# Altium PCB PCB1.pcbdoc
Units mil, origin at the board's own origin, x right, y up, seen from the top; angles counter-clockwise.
Board outline 5155 x 5410 mil, 2 copper layers (Top Layer, Bottom Layer); 94 components, 49 nets, 290 pads, 505 vias.
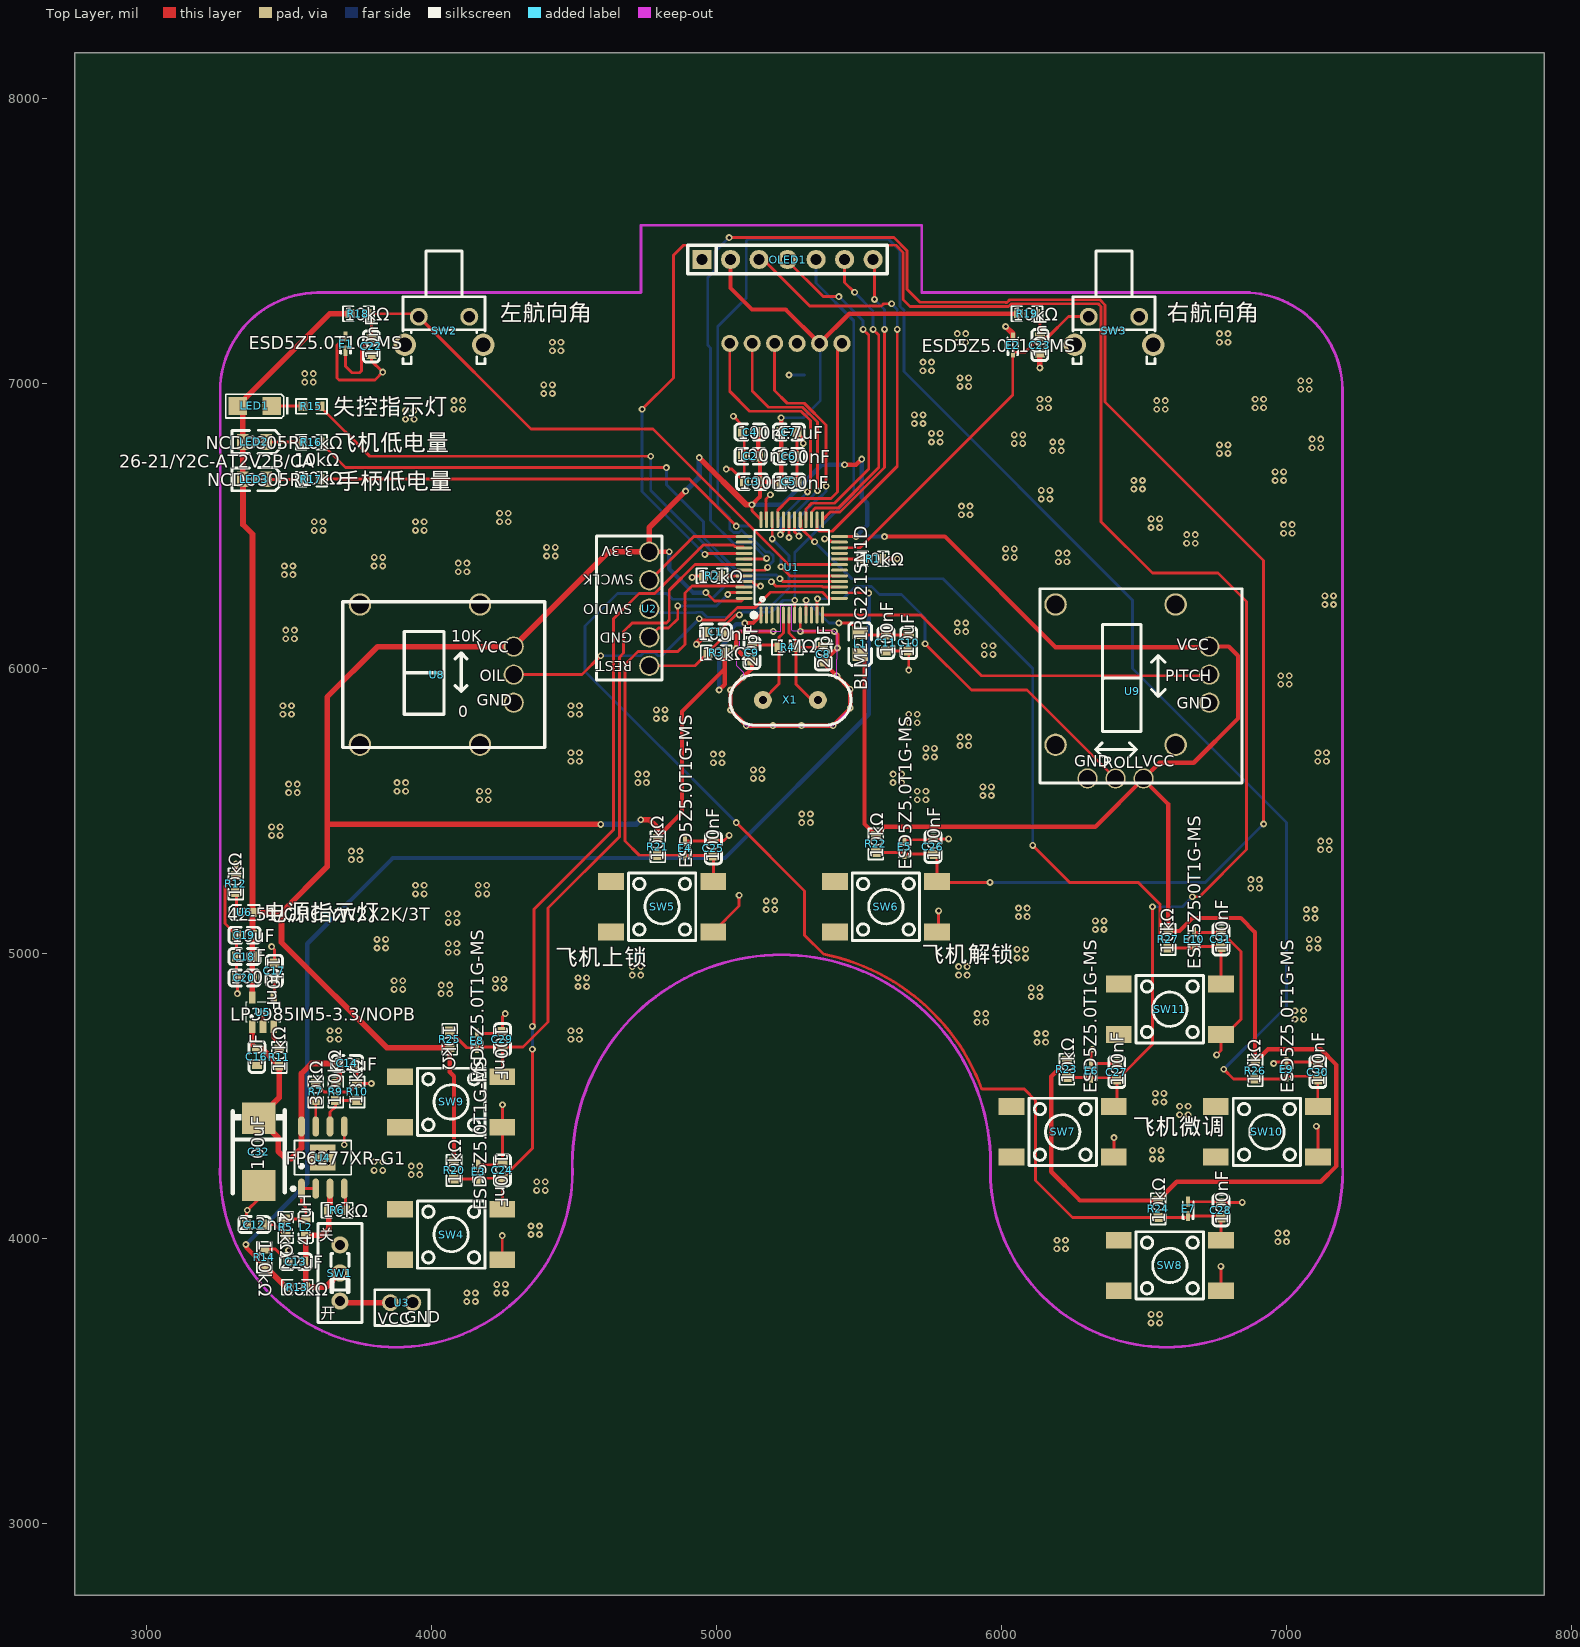
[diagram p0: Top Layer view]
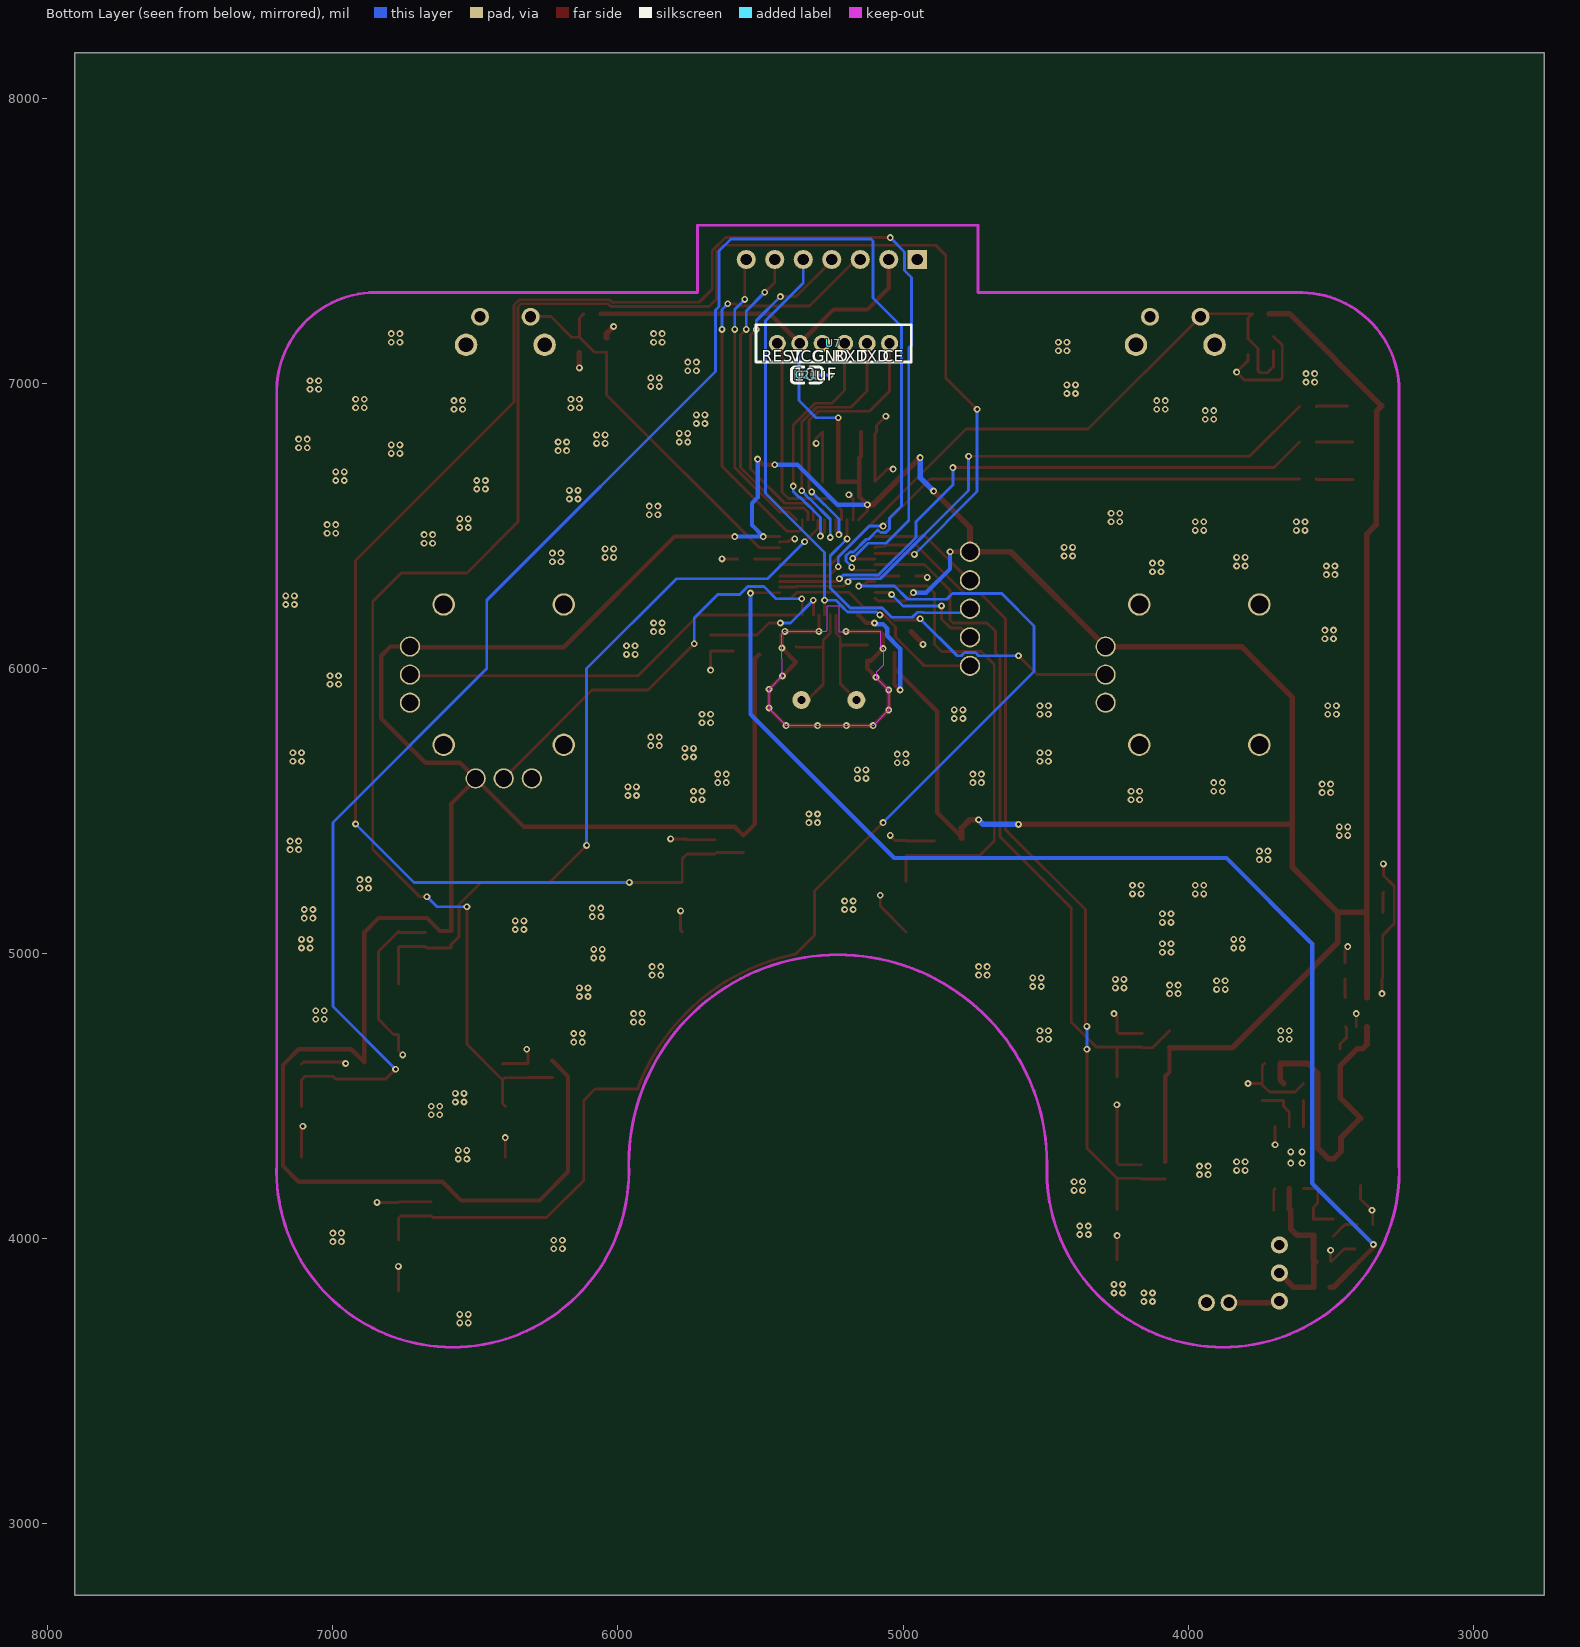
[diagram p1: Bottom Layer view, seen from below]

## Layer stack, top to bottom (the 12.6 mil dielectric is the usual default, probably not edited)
Top Layer: signal copper (thickness not stored)
Dielectric: dielectric 12.6, FR-4, Dk 4.8
Bottom Layer: signal copper (thickness not stored)

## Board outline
7905,2750 2750,2750 2750,8160 7905,8160

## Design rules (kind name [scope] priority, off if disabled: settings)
BoardOutlineClearance copperThickness1oz [All] p0: genericclearance=10 ignorepadtopadclearanceinfootprint=FALSE except(0: Arc-SplitContinuation Track-SplitContinuation SMDPad-SplitContinuation THPad-SplitContinuation Via-SplitContinuation Fill-SplitContinuation Poly-SplitContinuation Region-SplitContinuation Text-SplitContinuation; 6: Track-CutoutEdge SMDPad-CutoutEdge THPad-CutoutEdge Via-CutoutEdge Region-CutoutEdge; 11.8: Track-OutlineEdge SMDPad-OutlineEdge THPad-OutlineEdge Via-OutlineEdge Fill-OutlineEdge Region-OutlineEdge Poly-OutlineEdge Text-OutlineEdge Fill-CutoutEdge)
BoardOutlineClearance copperThickness2oz [All] p0: genericclearance=10 ignorepadtopadclearanceinfootprint=FALSE except(0: Arc-SplitContinuation Track-SplitContinuation SMDPad-SplitContinuation THPad-SplitContinuation Via-SplitContinuation Fill-SplitContinuation Poly-SplitContinuation Region-SplitContinuation Text-SplitContinuation; 6: Track-CutoutEdge SMDPad-CutoutEdge THPad-CutoutEdge Via-CutoutEdge Region-CutoutEdge; 11.8: Track-OutlineEdge SMDPad-OutlineEdge THPad-OutlineEdge Via-OutlineEdge Fill-OutlineEdge Region-OutlineEdge Poly-OutlineEdge Text-OutlineEdge Fill-CutoutEdge)
Clearance copperThickness1oz [(InNet('REST') OR InNet('OSC_OUT') OR InNet('OSC_IN') OR InNet('$1N3011') OR InNet('$1N4996') OR InNet('$1N6765') OR InNet('S1') OR InNet('S2') OR InNet('S3') OR InNet('S4') OR InNet('S5') OR InNet('S6') OR InNet('S7') OR InNet('S8') OR InNet('S9') OR InNet('S10') OR InNet('$1N4402') OR InNet('$1N8601') OR InNet('$1N8762') OR InNet('$1N8882') OR InNet('CS') OR InNet('MISO') OR InNet('MOSI') OR InNet('SCK') OR InNet('BOOT1') OR InNet('BOOT0') OR InNet('$1N5122') OR InNet('$1N5241') OR InNet('$1N5390') OR InNet('$1N6665') OR InNet('$1N8365') OR InNet('LED1') OR InNet('LED2') OR InNet('LED3') OR InNet('ROLL-ADC') OR InNet('PITCH-ADC') OR InNet('OIL-ADC') OR InNet('UART_TX') OR InNet('UART_RX') OR InNet('CE') OR InNet('RST') OR InNet('SWDIO') OR InNet('SWCLK'))] p1: gap=7 ignorepadtopadclearanceinfootprint=FALSE except(4: Track-Track; 6: Track-SMDPad SMDPad-SMDPad Track-THPad SMDPad-THPad THPad-THPad Track-Via SMDPad-Via THPad-Via Via-Via SMDPad-Fill THPad-Fill Via-Fill Fill-Fill Track-Region SMDPad-Region THPad-Region Via-Region Region-Region Track-Poly SMDPad-Poly THPad-Poly Via-Poly Fill-Poly Region-Poly Poly-Poly Track-Text SMDPad-Text THPad-Text Via-Text Fill-Text Region-Text Poly-Text Text-Text; 6.9: Track-Hole SMDPad-Hole THPad-Hole Via-Hole Fill-Hole Region-Hole Poly-Hole Text-Hole Sheet-Hole; 11.8: Track-Fill Fill-Region Track-Sheet SMDPad-Sheet THPad-Sheet Via-Sheet Fill-Sheet Region-Sheet Poly-Sheet Text-Sheet)
Clearance copperThickness2oz [(InNet('GND') OR InNet('3.3V') OR InNet('VCC') OR InNet('5V') OR InNet('BAT-ADC') OR InNet('BAT_IN'))] p1: gap=7 ignorepadtopadclearanceinfootprint=FALSE except(6: Track-SMDPad SMDPad-SMDPad Track-THPad SMDPad-THPad THPad-THPad Track-Via SMDPad-Via THPad-Via Via-Via SMDPad-Fill THPad-Fill Via-Fill Fill-Fill Track-Region SMDPad-Region THPad-Region Via-Region Region-Region Track-Poly SMDPad-Poly THPad-Poly Via-Poly Fill-Poly Region-Poly Poly-Poly Track-Text SMDPad-Text THPad-Text Via-Text Fill-Text Region-Text Poly-Text Text-Text; 6.9: Track-Hole SMDPad-Hole THPad-Hole Via-Hole Fill-Hole Region-Hole Poly-Hole Text-Hole Sheet-Hole; 8: Track-Track; 11.8: Track-Fill Fill-Region Track-Sheet SMDPad-Sheet THPad-Sheet Via-Sheet Fill-Sheet Region-Sheet Poly-Sheet Text-Sheet)
DiffPairsRouting differentialPair [All] p1: maxuncoupledlength=10 minlimit=5.9843 maxlimit=5.9843 mostfreqgap=5.9843 toplayer_minwidth=5 toplayer_prefwidth=10 toplayer_maxwidth=100 bottomlayer_minwidth=5 bottomlayer_prefwidth=10 bottomlayer_maxwidth=100
PasteMaskExpansion pasteMaskExpansion [All] p1: expansion=0
PlaneConnect innerPlane [All] p1: planeconnectstyle=Relief reliefexpansion=20 reliefentries=4 reliefconductorwidth=10 reliefairgap=10
PolygonConnect copperRegion [All] p1: connectstyle=Relief reliefentries=4 reliefconductorwidth=10 polygonreliefangle="90 Angle" airgapwidth=10
RoutingVias viaSize [All] p1: viastyle="Through Hole" holewidth=12.0078 minholewidth=11.811 maxholewidth=248.0314 width=24.0158 minwidth=19.685 maxwidth=393.7008
SolderMaskExpansion solderMaskExpansion [All] p1: useseparateexpansions=TRUE expansion=2.0079 expansionbottom=2.0079
Width copperThickness1oz [All] p1: maxlimit=20 minlimit=8 preferedwidth=10
Width copperThickness2oz [All] p1: maxlimit=20 minlimit=8 preferedwidth=10

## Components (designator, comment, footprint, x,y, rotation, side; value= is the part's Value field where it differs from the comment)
C1 "100nF" C0603 4998.32,6128.73 r180 top
C2 "100nF" C0603 5120,6745 r0 top
C3 "100nF" C0603 5125.72,6655.87 r0 top
C4 "100nF" C0603 5120,6830 r0 top
C5 "100nF" C0603 5255,6655 r180 top
C6 "100nF" C0603 5255,6745 r180 top
C7 "4.7uF" C0603 5255,6830 r180 top
C8 "20pF" C0603 5375,6050 r90 top
C9 "20pF" C0603 5125,6055 r90 top
C10 "10uF" C0603 5675,6090 r90 top
C11 "100nF" C0603 5595,6090 r90 top
C12 "2.2nF" C0603 3380,4050 r180 top
C13 "22uF" C0603 3525,3920 r0 top
C14 "22uF" C0603 3705,4615 r180 top
C16 "1uF" C0603 3388.47,4638.47 r90 top
C17 "100nF" C0603 3450,4940 r270 top
C18 "1uF" C0603 3345,4990 r0 top
C19 "10uF" C0603 3345,5065 r0 top
C20 "100nF" C0603 3345,4915 r0 top
C21 "10uF" C0603 5337,7030 r180 bottom
C22 "10nF" C0603 3790,7130 r90 top
C23 "10nF" C0603 6135,7135 r90 top
C24 "100nF" C0603 4250,4240 r270 top
C25 "100nF" C0603 4990,5370 r270 top
C26 "100nF" C0603 5760,5375 r270 top
C27 "100nF" C0603 6405,4585 r270 top
C28 "100nF" C0603 6770,4100 r270 top
C29 "100nF" C0603 4250,4700 r270 top
C30 "100nF" C0603 7110,4585 r270 top
C31 "100nF" C0603 6770,5050 r270 top
C32 "100uF" CASE-D_7343 3395,4305 r90 top
E1 "ESD5Z5.0T1G-MS" SOD-523_L1.2-W0.8-LS1.6-RD 3700,7140 r90 top
E2 "ESD5Z5.0T1G-MS" SOD-523_L1.2-W0.8-LS1.6-RD 6040,7135 r90 top
E3 "ESD5Z5.0T1G-MS" SOD-523_L1.2-W0.8-LS1.6-RD 4165,4235 r90 top
E4 "ESD5Z5.0T1G-MS" SOD-523_L1.2-W0.8-LS1.6-RD 4890,5370 r90 top
E5 "ESD5Z5.0T1G-MS" SOD-523_L1.2-W0.8-LS1.6-RD 5660,5375 r90 top
E6 "ESD5Z5.0T1G-MS" SOD-523_L1.2-W0.8-LS1.6-RD 6315,4590 r90 top
E7 "ESD5Z5.0T1G-MS" SOD-523_L1.2-W0.8-LS1.6-RD 6655,4105 r90 top
E8 "ESD5Z5.0T1G-MS" SOD-523_L1.2-W0.8-LS1.6-RD 4160,4695 r90 top
E9 "ESD5Z5.0T1G-MS" SOD-523_L1.2-W0.8-LS1.6-RD 7000,4595 r90 top
E10 "ESD5Z5.0T1G-MS" SOD-523_L1.2-W0.8-LS1.6-RD 6675,5050 r90 top
L1 "BLM21PG221SN1D" L0805 5504.71,6087.46 r90 top
L2 "4.7uH" L0603 3560,4040 r90 top
LED1 "26-21/Y2C-AT2V2B/CA" LED1206-RD 3380.87,6921.47 r180 top
LED2 "NCD0805R1" LED0805-R-RD 3379.98,6795 r180 top
LED3 "NCD0805R1" LED0805-R-RD 3379.98,6663.9 r180 top
OLED1 "HS96L01W4S03" OLED-TH_HS96L01W4S03 5250,7435 r0 top
R1 "10kΩ" R0603 5550,6385 r0 top
R2 "10kΩ" R0603 4985,6325 r180 top
R3 "10kΩ" R0603 5000,6055 r180 top
R4 "1MΩ" R0603 5250,6075 r180 top
R5 "24kΩ" R0603 3490,4040 r270 top
R6 "10kΩ" R0603 3670,4100 r0 top
R7 "30kΩ" R0603 3595,4515 r90 top
R9 "100kΩ" R0603 3665,4515 r90 top
R10 "13kΩ" R0603 3740,4515 r270 top
R11 "10kΩ" R0603 3466.95,4636.04 r90 top
R12 "10kΩ" R0603 3315,5245 r90 top
R13 "68kΩ" R0603 3530,3830 r0 top
R14 "120kΩ" R0603 3415,3935 r270 top
R15 "10kΩ" R0603 3580,6920 r180 top
R16 "10kΩ" R0603 3580,6794.46 r180 top
R17 "10kΩ" R0603 3580,6665 r180 top
R18 "10kΩ" R0603 3745,7245 r180 top
R19 "10kΩ" R0603 6090,7245 r180 top
R20 "10kΩ" R0603 4080,4240 r90 top
R21 "10kΩ" R0603 4795,5375 r90 top
R22 "10kΩ" R0603 5560,5385 r90 top
R23 "10kΩ" R0603 6230,4595 r90 top
R24 "10kΩ" R0603 6550,4105 r90 top
R25 "10kΩ" R0603 4065,4700 r270 top
R26 "10kΩ" R0603 6890,4590 r90 top
R27 "10kΩ" R0603 6585,5050 r90 top
SW1 "开关" SW-TH_SS-12D01-GX 3680,3880 r90 top
SW2 "K2-1102AQ-H4CW-01" SW-TH_K2-1102BQ-G4CW-01 4045,7185 r180 top
SW3 "K2-1102AQ-H4CW-01" SW-TH_K2-1102BQ-G4CW-01 6395,7185 r180 top
SW4 "KH-6X6X5H-STM" SW-SMD_4P-L6.0-W6.0-P4.50-LS9.0-2 4070,4015 r0 top
SW5 "KH-6X6X5H-STM" SW-SMD_4P-L6.0-W6.0-P4.50-LS9.0-2 4810,5165 r0 top
SW6 "KH-6X6X5H-STM" SW-SMD_4P-L6.0-W6.0-P4.50-LS9.0-2 5595,5165 r0 top
SW7 "KH-6X6X5H-STM" SW-SMD_4P-L6.0-W6.0-P4.50-LS9.0-2 6215,4375 r0 top
SW8 "KH-6X6X5H-STM" SW-SMD_4P-L6.0-W6.0-P4.50-LS9.0-2 6590.9,3906.62 r0 top
SW9 "KH-6X6X5H-STM" SW-SMD_4P-L6.0-W6.0-P4.50-LS9.0-2 4070,4480 r0 top
SW10 "KH-6X6X5H-STM" SW-SMD_4P-L6.0-W6.0-P4.50-LS9.0-2 6931.39,4374.99 r0 top
SW11 "KH-6X6X5H-STM" SW-SMD_4P-L6.0-W6.0-P4.50-LS9.0-2 6590.9,4805.29 r0 top
U1 "STM32F103C8T6" LQFP-48_L7.0-W7.0-P0.50-LS9.0-BL 5265,6355 r0 top
U2 "stm32f103下载口" stm32f103swd下载口 4765,6410 r270 top
U3 "电源插座" 电源插座 3856.9,3776.14 r0 top
U4 "FP6277XR-G1" SOP-8_L4.9-W3.9-P1.27-LS6.0-BL-EP 3620,4285 r0 top
U5 "LP3985IM5-3.3/NOPB" SOT-23-5_L3.0-W1.7-P0.95-LS2.8-BR 3410,4795 r270 top
U6 "42-51/GHC-YW2X2K/3T" LED-SMD_L1.6-W0.8-FD_GREEN-1 3345,5145 r180 top
U7 "2.4G转串口" 2.4G转串口 5441,7141.04 r180 bottom
U8 "10K摇杆油门不回中" 10K摇杆油门不回中 3750,6225 r0 top
U9 "10K摇杆油门回中" 10K摇杆油门回中 6190,6225 r0 top
X1 "X49SD8MSD2SC" OSC-TH_L10.0-W4.5-P5.00 5260,5890 r270 top

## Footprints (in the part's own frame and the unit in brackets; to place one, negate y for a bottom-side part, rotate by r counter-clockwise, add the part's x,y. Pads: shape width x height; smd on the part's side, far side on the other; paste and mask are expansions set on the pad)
2.4G转串口 [mil]
  round 60 hole 36: 1(0,0) 2(78.74,0) 3(157.48,0) 4(236.22,0) 5(314.96,0) 6(393.7,0)
  silkscreen extent -75,-65 470,65
10K摇杆油门不回中 [mm]
  round 2 hole 1.6: 0(0,-12.5) 0(0,0) 0(10.7,-12.5) 0(10.7,0)
  round 1.8 hole 1.5: 1(13.7,-3.75) 2(13.7,-6.25) 3(13.7,-8.75)
  silkscreen extent -1.52,-12.75 16.48,0.25
10K摇杆油门回中 [mm]
  round 2 hole 1.6: 0(0,-12.5) 0(0,0) 0(10.7,-12.5) 0(10.7,0)
  round 1.8 hole 1.5: 1(13.7,-3.75) 2(13.7,-6.25) 3(13.7,-8.75) 4(2.85,-15.5) 5(5.35,-15.5) 6(7.85,-15.5)
  silkscreen extent -1.4,-15.9 16.6,1.4
C0603 [mm]
  rect 0.8x0.9 smd: 1(-0.7,0) 2(0.7,0)
  silkscreen extent -1.39,-0.71 1.39,0.71
CASE-D_7343 [mil]
  rect 110.2x118.5 smd: 1(118.11,0) 2(-118.11,0)
  silkscreen extent -146,-91 146,91
L0603 [mm]
  rect 0.8x0.864 smd: 1(-0.7,0) 2(0.7,0)
  silkscreen extent -1.42,-0.65 1.42,0.65
L0805 [mil]
  rect 44.59x54.21 smd: 1(-38.04,0) 2(38.04,0)
  silkscreen extent -77,-40 73,40
LED0805-R-RD [mm]
  rect 1x1.4 smd: 1(1.05,0) 2(-1.05,0)
  silkscreen extent -2.22,-1.04 1.99,1.01
LED1206-RD [mm]
  rect 1.635x1.6 smd: 1(-1.517,0) 2(1.517,0)
  silkscreen extent -2.99,-1.04 2.57,1.07
LED-SMD_L1.6-W0.8-FD_GREEN-1 [mm]
  rect 0.7x0.8 smd: 1(-0.715,0) 2(0.715,0)
  silkscreen extent -1.35,-0.65 1.35,0.7
LQFP-48_L7.0-W7.0-P0.50-LS9.0-BL [mm]
  oval 0.27x1.5 smd: 1(-2.75,-4.25) 2(-2.25,-4.25) 3(-1.75,-4.25) 4(-1.25,-4.25) 5(-0.75,-4.25) 6(-0.25,-4.25) 7(0.25,-4.25) 8(0.75,-4.25) 9(1.25,-4.25) 10(1.75,-4.25) 11(2.25,-4.25) 12(2.75,-4.25) 25(2.75,4.25) 26(2.25,4.25) 27(1.75,4.25) 28(1.25,4.25) 29(0.75,4.25) 30(0.25,4.25) 31(-0.25,4.25) 32(-0.75,4.25) 33(-1.25,4.25) 34(-1.75,4.25) 35(-2.25,4.25) 36(-2.75,4.25)
  oval 1.5x0.27 smd: 13(4.25,-2.75) 14(4.25,-2.25) 15(4.25,-1.75) 16(4.25,-1.25) 17(4.25,-0.75) 18(4.25,-0.25) 19(4.25,0.25) 20(4.25,0.75) 21(4.25,1.25) 22(4.25,1.75) 23(4.25,2.25) 24(4.25,2.75) 37(-4.25,2.75) 38(-4.25,2.25) 39(-4.25,1.75) 40(-4.25,1.25) 41(-4.25,0.75) 42(-4.25,0.25) 43(-4.25,-0.25) 44(-4.25,-0.75) 45(-4.25,-1.25) 46(-4.25,-1.75) 47(-4.25,-2.25) 48(-4.25,-2.75)
  silkscreen extent -3.59,-4.46 3.3,3.34
OLED-TH_HS96L01W4S03 [mm]
  rect 1.7x1.7 hole 1: 1(-7.62,0)
  round 1.7 hole 1: 2(-5.08,0) 3(-2.54,0) 4(0,0) 5(2.54,0) 6(5.08,0) 7(7.62,0)
  silkscreen extent -8.89,-1.27 8.89,1.29
OSC-TH_L10.0-W4.5-P5.00 [mm]
  round 1.6 hole 0.7: 1(0,2.45) 2(0,-2.45)
  silkscreen extent -2.25,-5.39 2.25,5.39
R0603 [mil]
  rect 31.75x34.02 smd: 1(-29.66,0) 2(29.66,0)
  silkscreen extent -55,-26 55,26
SOD-523_L1.2-W0.8-LS1.6-RD [mm]
  rect 0.93x0.36 smd: 1(-0.635,0) 2(0.635,0)
  silkscreen extent -0.91,-0.55 0.68,0.55
SOP-8_L4.9-W3.9-P1.27-LS6.0-BL-EP [mm]
  oval 0.6x1.8 smd: 1(-1.905,-2.772) 2(-0.635,-2.772) 3(0.635,-2.772) 4(1.905,-2.772) 5(1.905,2.772) 6(0.635,2.772) 7(-0.635,2.772) 8(-1.905,2.772)
  rect 2.29x2.29 smd: 9(0,0)
  silkscreen extent -2.8,-2.92 2.53,1.52
SOT-23-5_L3.0-W1.7-P0.95-LS2.8-BR [mm]
  rect 1.1x0.6 smd: 1(1.3,-0.95) 2(1.3,0) 3(1.3,0.95) 4(-1.3,0.95) 5(-1.3,-0.95)
  silkscreen extent -0.9,-1.55 0.9,1.55
stm32f103swd下载口 [mm]
  round 1.8 hole 1.5: 1(0,0) 2(2.54,0) 3(5.08,0) 4(7.62,0) 5(10.16,0)
  silkscreen extent -1.4,-4.7 11.43,1.14
SW-SMD_4P-L6.0-W6.0-P4.50-LS9.0-2 [mm]
  rect 2.3x1.5 smd: 1(-4.55,2.25) 2(4.55,2.25) 3(-4.55,-2.25) 4(4.55,-2.25)
  silkscreen extent -3,-3 3,3
SW-TH_K2-1102BQ-G4CW-01 [mm]
  round 1.6 hole 1: 1(-2.25,-1.25) 2(2.25,-1.25)
  round 2 hole 1.3: 3(3.5,1.25) 4(-3.5,1.25)
  silkscreen extent -3.65,-7.1 3.65,2.94
SW-TH_SS-12D01-GX [mil]
  round 60 hole 36: 1(-98.43,0) 2(-0.01,0) 3(98.42,0)
  silkscreen extent -173,-77 173,77
电源插座 [mm]
  round 1.5 hole 1: 1(0,0) 2(2,0)
  silkscreen extent -1.4,-2.03 3.43,1.14

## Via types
v1: diameter 24.02, hole 12.01, Top Layer to Bottom Layer, 501 vias
v2: diameter 24, hole 12, Top Layer to Bottom Layer, 4 vias

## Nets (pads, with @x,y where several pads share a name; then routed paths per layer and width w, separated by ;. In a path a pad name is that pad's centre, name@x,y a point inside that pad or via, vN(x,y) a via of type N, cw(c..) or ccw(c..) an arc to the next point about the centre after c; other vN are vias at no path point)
3.3V: C2.2 C3.2 C4.2 C5.2 C6.2 C7.2 C18.2 C19.2 C20.2 C21.1 L1.1 LED1.2 LED2.1 LED3.1 OLED1.2 R3.1 R18.2 R19.2 R20.2 R21.2 R22.2 R23.2 R24.2 R25.2 R26.2 R27.2 U1.1 U1.24 U1.36 U1.48 U2.1 U5.5 U6.1 U7.2 U8.1 U9.1 U9.6 | length 20067.9
  Top Layer w10: v1(4963.74,6266.5) 4993.51,6236.73 5087.68,6236.73 U1.48 ; v1(5125,6575) 5125,6554.05 U1.36 ; U1.24 v1(5490,6463.27)
  Top Layer w14.96: R25.2 4065,4585 4080,4570 R20.2 ; U2.1 v1(4835,6410) ; R21.2@4795,5410 4880,5495 4880,5850 5030,6000 ; v1(5010,5925) 5030,5945 5030,6000 ; R3.1 5030,6054.66 5030,6000 ; OLED1.2 5050,7335 5125,7260 5243.3,7260 U7.2 5466.22,7245 R19.2 ; v1(5100,6160) 5129.05,6160 U1.1 ; v1(5125,6575) 5153.28,6603.28 C3.2 ; C4.2 C2.2 5153.28,6739.28 C3.2 ; v1(5227.44,6880) C7.2 C6.2 C5.2 5226.57,6655.87 C3.2 ; v1(5450,6715) 5490,6715 v1(5510,6735) ; L1.1 5519.67,6034.46 5519.67,5454.99 R22.2 5590.34,5445 6329.29,5445 U9.6 ; v1(5590,6463.27) 5801.73,6463.27 6190,6075 6727.01,6075 U9.1 6797.64,6077.36 6830,6045 6830,5825 6675,5670 6554.29,5670 U9.6 ; R23.2 6175,4569.66 6175,4235 6275.34,4134.66 R24.2 6615.34,4200 7120,4200 7175,4255 7175,4610 7120,4665 6935.34,4665 R26.2 6890,5075 6840,5125 6670,5125 6624.66,5079.66 R27.2 6585,5525 6499.06,5610.94 U9.6
  Top Layer w19.68: C20.2 C18.2 C19.2 3373.15,5065.59 U6.1 ; U5.5 C20.2 ; R18.2 3644.66,7245 LED1.2 3338.63,6903.97 LED2.1 LED3.1 3340,6662.53 3340,6505 3373.15,6471.85 U6.1 ; R25.2 3844.66,4670.34 3475,5040 3475,5145 ; v1(4595,5453.72) 3635,5453.72 ; v1(4735,5470) 4766.05,5470 4795,5441.05 4795,5410 R21.2 ; v1(4892.5,6622.5) 4765,6495 U2.1 4622.01,6410 U8.1 3812.36,6077.36 3635,5900 3635,5453.72 ; v1(4940,6740) 5105,6575 v1(5125,6575) ; U6.1 3475,5145 ; 3475,5145 3635,5305 3635,5453.72
  Bottom Layer w9.84: v1(5227.44,6880) 5305,6880 5365,6940 5365,7029.56 C21.1 5364.56,7138.74 U7.2
  Bottom Layer w14.96: v1(4835,6410) 4835,6350 4918.5,6266.5 v1(4963.74,6266.5) ; v1(5010,5925) 5010,6070 5055.11,6115.11 5055.11,6141.13 5070.03,6156.05 5096.05,6156.05 v1(5100,6160) ; v1(5125,6575) 5230,6575 5370,6715 v1(5450,6715) ; v1(5510,6735) 5510,6600 5530,6580 5530,6503.27 v1(5490,6463.27) v1(5590,6463.27)
  Bottom Layer w19.68: v1(4595,5453.72) 4718.72,5453.72 v1(4735,5470) ; v1(4892.5,6622.5) 4940,6670 v1(4940,6740)
5V: C14.2 C16.2 C32.1 R9.2 R11.1 U4.8 U5.1 | length 1137.7
  Top Layer w19.68: U5.1 3372.6,4681.9 C16.2 3407.31,4666.03 R11.1 3466.95,4495.06 C32.1 3463.56,4354.55 3463.56,4306.44 3488.92,4281.08 3508.6,4281.08 3545,4317.48 U4.8 3545,4580 3580,4615 C14.2 3677.44,4557.1 R9.2
$1N3011: C10.2 C11.2 L1.2 U1.9 | length 463.4
  Top Layer w9.84: U1.9 5314.21,6239.21 v1(5315,6240) ; v1(5430,6160) 5470.21,6160 L1.2 5512.65,6117.56 C11.2 C10.2
  Bottom Layer w9.84: v1(5315,6240) 5395,6160 v1(5430,6160)
$1N4402: L2.2 R5.1 U4.1 U4.2 | length 235.4
  Top Layer w10: R5.1 3557.89,4069.66 L2.2 3560,4110 3545,4125 U4.1 U4.2
$1N4996: C12.1 R5.2 | length 98.9
  Top Layer w10: C12.1 3450.34,4050 R5.2
$1N5122: R6.2 U4.4 | length 77.8
  Top Layer w10: U4.4 3699.66,4171.19 R6.2
$1N5241: R7.1 U4.7 | length 91.2
  Top Layer w10: U4.7 R7.1
$1N5390: R9.1 R10.2 U4.6 | length 174.5
  Top Layer w10: U4.6 3645,4445 3665,4465 R9.1 R10.2
$1N6665: R11.2 U5.3 | length 88.2
  Top Layer w10: U5.3 3445,4741.41 3445,4705 3466.95,4683.05 R11.2
$1N6765: C17.2 U5.4 | length 67.3
  Top Layer w10: U5.4 3450,4848.78 C17.2
$1N8365: R12.1 U6.2 | length 71.1
  Top Layer w10: R12.1 3316.85,5213.49 U6.2
$1N8601: LED1.1 R15.2 | length 110.3
  Top Layer w10: LED1.1 3548.87,6921.47 R15.2
$1N8762: LED2.2 R16.2 | length 129.2
  Top Layer w10: LED2.2 3549.8,6795 R16.2
$1N8882: LED3.2 R17.2 | length 129.5
  Top Layer w10: LED3.2 3549.24,6663.9 R17.2
BAT-ADC: R13.1 R14.2 U1.14 | length 4193.9
  Top Layer w9.84: U1.14 5533.58,6266.42 v1(5535,6265)
  Top Layer w14.96: v1(3350,3980) 3350,3970.34 R14.2
  Top Layer w19.68: R14.2 3490.34,3830 R13.1
  Bottom Layer w14.96: v1(3350,3980) 3565,4195 3565,5035 3865.58,5335.58 5030.58,5335.58 5535,5840 v1(5535,6265)
BAT_IN: SW1.1 U3.1 | length 179.2
  Top Layer w19.68: SW1.1 3685.43,3776.14 U3.1
BOOT0: R2.1 U1.44 | length 83.2
  Top Layer w10: R2.1 5097.21,6325 U1.44
BOOT1: R1.1 U1.20 | length 88.2
  Top Layer w10: U1.20 5519.87,6384.53 R1.1
CE: U1.32 U7.6 | length 993.7
  Top Layer w10: U7.6 5047.3,6972.7 5117.01,6902.99 5297.01,6902.99 5330,6870 5330,6630 v1(5320,6620) ; v1(5225,6470) 5235.47,6480.47 U1.32
  Bottom Layer w10: v1(5225,6470) 5225,6525 v1(5320,6620)
CS: OLED1.7 U1.25 | length 1038.9
  Top Layer w10: U1.25 5399.77,6548.82 5433.64,6548.82 5590,6705.18 v1(5590,7190) ; OLED1.7 5555,7430 v1(5555,7295)
  Bottom Layer w10: v1(5555,7295) 5590,7260 v1(5590,7190)
GND: C1.2 C2.1 C3.1 C4.1 C5.1 C6.1 C7.1 C8.1 C9.1 C10.1 C11.1 C12.2 C13.1 C14.1 C16.1 C17.1 C18.1 C19.1 C20.1 C21.2 C22.1 C23.1 C24.1 C25.1 C26.1 C27.1 C28.1 C29.1 C30.1 C31.1 C32.2 E1.2 E2.2 E3.2 E4.2 E5.2 E6.2 E7.2 E8.2 E9.2 E10.2 OLED1.1 R1.2 R2.2 R7.2 R10.1 R12.2 R14.1 SW2.1 SW3.1 SW4.4 SW5.4 SW6.4 SW7.4 SW8.4 SW9.4 SW10.4 SW11.4 U1.8 U1.23 U1.35 U1.47 U2.4 U3.2 U4.5 U4.9 U5.2 U7.3 U8.3 U9.3 U9.4 | length 7152.1
  Top Layer w10: v1(3315,5315) R12.2 3276.81,5236.47 3276.81,5105.63 C19.1 C18.1 C20.1 3320,4912.44 v1(3320,4860) ; C12.2 3352.44,4097.44 v1(3355,4100) 3395,4140 C32.2 ; U5.2 v1(3410,4790) ; R14.1 3452.78,3964.66 C13.1 3500,3922.56 v1(3500,3960) ; v1(3440,5025) 3450,5015 C17.1 ; R7.2 3624.66,4515 3715,4515 3740,4540 R10.1 ; v1(3695,4330) U4.5 ; E1.2 3670,7135 3670,7020 3677.07,7012.93 3802.93,7012.93 v1(3830,7040) 3790,7080 C22.1 ; C14.1 3740,4607.56 R10.1 ; v1(3790,4544.66) R10.1 ; E8.2 4242.44,4720 C29.1 4250,4780 v1(4260,4790) ; E3.2 4242.44,4260 C24.1 4250,4390.55 SW9.4 4250,4392.28 v1(4250,4470) ; SW4.4 v1(4249.13,4011.41) ; U2.4 4797.01,6142.01 4832.45,6142.01 4865,6174.56 v1(4865,6220) ; E4.2 4987.44,5395 C25.1 5027.56,5397.56 v1(5045,5415) ; v1(4915,6320) 4920,6325 R2.2 ; SW5.4 5080,5167.28 v1(5080,5205) ; v1(5035,6700) 5054.03,6700 C3.1 5098.16,6824.28 C4.1 5092.44,6852.56 v1(5060,6885) ; v1(5040,6260) 5046.42,6266.42 U1.47 ; U1.35 5174.72,6524.02 5174.72,6594.72 v1(5190,6610) ; C5.1 C6.1 C7.1 5305,6807.56 v1(5305,6790) ; U1.8 5294.53,6131.05 v1(5295,6130.58) ; v1(5380,6455) 5393.33,6455 5403.05,6445.28 5430.62,6445.28 U1.23 ; R1.2 v1(5635,6385) ; C11.1 C10.1 v1(5675,5995) ; E5.2 5757.44,5400 C26.1 v1(5815,5402.56) ; SW6.4 5780,5082.28 v1(5780,5150) ; v1(6320,4665) 6315,4660 E6.2 6402.56,4615 C27.1 ; SW7.4 6395,4287.28 v1(6395,4355) ; E7.2 6767.56,4130 C28.1 v1(6845,4127.56) ; E10.2 6767.44,5075 C31.1 6840,5007.56 6840,4770 6786.71,4716.71 SW11.4 6770.03,4660.03 v1(6755,4645) ; SW8.4 v1(6770.03,3903.03) ; v1(6955,4615) 6960,4620 E9.2 7102.56,4620 C30.1 ; v1(7105,4395) 7110.52,4389.48 SW10.4
  Top Layer w14.96: v1(5200,6130.58) 5080.58,6130.58 5070,6120 v1(5070,6070) 5112.56,6027.44 C9.1 5125,6000 v1(5094.75,5969.75) v1(5050,5925) v1(5050,5855) v1(5105,5800) v1(5198.66,5800) v1(5299.49,5800) v1(5410,5800) 5470,5860 v1(5470,5927.44) v1(5422.85,5974.59) C8.1 v1(5425,6072.44) 5425,6120 v1(5414.42,6130.58) ; v1@5295.05,6130.53 v1@5414.37,6130.53
  Top Layer w19.68: v1(4930,6085) 4930,6087.96 C1.2 ; v1(6015,7200) 6040,7175 E2.2 ; v1(6135,7055) C23.1
  Bottom Layer w10: v1(4865,6220) 5000,6220 v1(5040,6260) ; v1(5255,7030) C21.2
  other v1: 6524.97,3704.98 6555.03,3704.98 6525.03,3735.02 6555.03,3735.02 4124.97,3779.98 4155.03,3779.98 4125.03,3810.02 4155.03,3810.02 4229.97,3809.98 4260.03,3809.98 4230.03,3840.02 4260.03,3840.02 6194.97,3964.98 6225.03,3964.98 6969.97,3989.98 7000.03,3989.98 6195.03,3995.02 6225.03,3995.02 4349.97,4014.98 4380.03,4014.98 6970.03,4020.02 7000.03,4020.02 4350.03,4045.02 4380.03,4045.02 4369.97,4169.98 4400.03,4169.98 4370.03,4200.02 4400.03,4200.02 3929.97,4224.98 3960.03,4224.98 3799.97,4239.98 3830.03,4239.98 3930.03,4255.02 3960.03,4255.02 3800.03,4270.02 3830.03,4270.02 6529.97,4279.98 6560.03,4279.98 6530.03,4310.02 6560.03,4310.02 6624.97,4434.98 6655.03,4434.98 6625.03,4465.02 6655.03,4465.02 6539.97,4479.98 6570.03,4479.98 6540.03,4510.02 6570.03,4510.02 6124.97,4689.98 6155.03,4689.98 3644.97,4699.98 3675.03,4699.98 4489.97,4699.98 4520.03,4699.98 6125.03,4720.02 6155.03,4720.02 3645.03,4730.02 3675.03,4730.02 4490.03,4730.02 4520.03,4730.02 5914.97,4759.98 5945.03,4759.98 7029.97,4769.98 7060.03,4769.98 5915.03,4790.02 5945.03,4790.02 7030.03,4800.02 7060.03,4800.02 6104.97,4849.98 6135.03,4849.98 4034.97,4859.98 4065.03,4859.98 3869.97,4874.98 3900.03,4874.98 4224.97,4879.98 4255.03,4879.98 6105.03,4880.02 6135.03,4880.02 4514.97,4884.98 4545.03,4884.98 4035.03,4890.02 4065.03,4890.02 3870.03,4905.02 3900.03,4905.02 4225.03,4910.02 4255.03,4910.02 4515.03,4915.02 4545.03,4915.02 4704.97,4924.98 4735.03,4924.98 5849.97,4924.98 5880.03,4924.98 4705.03,4955.02 4735.03,4955.02 5850.03,4955.02 5880.03,4955.02 6054.97,4984.98 6085.03,4984.98 4059.97,5004.98 4090.03,5004.98 6055.03,5015.02 6085.03,5015.02 3809.97,5019.98 3840.03,5019.98 7079.97,5019.98 7110.03,5019.98 4060.03,5035.02 4090.03,5035.02 3810.03,5050.02 3840.03,5050.02 7080.03,5050.02 7110.03,5050.02 6329.97,5084.98 6360.03,5084.98 4059.97,5109.98 4090.03,5109.98 6330.03,5115.02 6360.03,5115.02 7069.97,5124.98 7100.03,5124.98 6059.97,5129.98 6090.03,5129.98 4060.03,5140.02 4090.03,5140.02 5174.97,5154.98 5205.03,5154.98 7070.03,5155.02 7100.03,5155.02 6060.03,5160.02 6090.03,5160.02 5175.03,5185.02 5205.03,5185.02 3944.97,5209.98 3975.03,5209.98 4164.97,5209.98 4195.03,5209.98 6874.97,5229.98 6905.03,5229.98 3945.03,5240.02 3975.03,5240.02 4165.03,5240.02 4195.03,5240.02 6875.03,5260.02 6905.03,5260.02 3719.97,5329.98 3750.03,5329.98 3720.03,5360.02 3750.03,5360.02 7119.97,5364.98 7150.03,5364.98 7120.03,5395.02 7150.03,5395.02 3439.97,5414.98 3470.03,5414.98 3440.03,5445.02 3470.03,5445.02 5299.97,5459.98 5330.03,5459.98 5300.03,5490.02 5330.03,5490.02 4169.97,5539.98 4200.03,5539.98 5704.97,5539.98 5735.03,5539.98 5934.97,5554.98 5965.03,5554.98 3499.97,5564.98 3530.03,5564.98 3879.97,5569.98 3910.03,5569.98 4170.03,5570.02 4200.03,5570.02 5705.03,5570.02 5735.03,5570.02 5935.03,5585.02 5965.03,5585.02 3500.03,5595.02 3530.03,5595.02 3880.03,5600.02 3910.03,5600.02 4724.97,5599.98 4755.03,5599.98 5619.97,5599.98 5650.03,5599.98 5129.97,5614.98 5160.03,5614.98 4725.03,5630.02 4755.03,5630.02 5620.03,5630.02 5650.03,5630.02 5130.03,5645.02 5160.03,5645.02 4989.97,5669.98 5020.03,5669.98 4489.97,5674.98 4520.03,5674.98 7109.97,5674.98 7140.03,5674.98 5734.97,5689.98 5765.03,5689.98 4990.03,5700.02 5020.03,5700.02 4490.03,5705.02 4520.03,5705.02 7110.03,5705.02 7140.03,5705.02 5735.03,5720.02 5765.03,5720.02 5854.97,5729.98 5885.03,5729.98 5855.03,5760.02 5885.03,5760.02 5674.97,5809.98 5705.03,5809.98 4789.97,5824.98 4820.03,5824.98 3479.97,5839.98 3510.03,5839.98 4489.97,5839.98 4520.03,5839.98 5675.03,5840.02 5705.03,5840.02 4790.03,5855.02 4820.03,5855.02 5470,5862.49 3480.03,5870.02 3510.03,5870.02 4490.03,5870.02 4520.03,5870.02 6979.97,5944.98 7010.03,5944.98 6980.03,5975.02 7010.03,5975.02 5939.97,6049.98 5970.03,6049.98 5940.03,6080.02 5970.03,6080.02 3489.97,6104.98 3520.03,6104.98 5844.97,6129.98 5875.03,6129.98 3490.03,6135.02 3520.03,6135.02 5845.03,6160.02 5875.03,6160.02 7134.97,6224.98 7165.03,6224.98 7135.03,6255.02 7165.03,6255.02 3484.97,6329.98 3515.03,6329.98 4094.97,6339.98 4125.03,6339.98 3485.03,6360.02 3515.03,6360.02 3799.97,6359.98 3830.03,6359.98 4095.03,6370.02 4125.03,6370.02 6199.97,6374.98 6230.03,6374.98 3800.03,6390.02 3830.03,6390.02 6014.97,6389.98 6045.03,6389.98 4404.97,6394.98 4435.03,6394.98 6200.03,6405.02 6230.03,6405.02 6015.03,6420.02 6045.03,6420.02 4405.03,6425.02 4435.03,6425.02 6649.97,6439.98 6680.03,6439.98 6650.03,6470.02 6680.03,6470.02 6989.97,6474.98 7020.03,6474.98 3589.97,6484.98 3620.03,6484.98 3944.97,6484.98 3975.03,6484.98 6524.97,6494.98 6555.03,6494.98 6990.03,6505.02 7020.03,6505.02 3590.03,6515.02 3620.03,6515.02 3945.03,6515.02 3975.03,6515.02 4239.97,6514.98 4270.03,6514.98 6525.03,6525.02 6555.03,6525.02 5859.97,6539.98 5890.03,6539.98 4240.03,6545.02 4270.03,6545.02 5860.03,6570.02 5890.03,6570.02 6139.97,6594.98 6170.03,6594.98 6140.03,6625.02 6170.03,6625.02 6464.97,6629.98 6495.03,6629.98 6465.03,6660.02 6495.03,6660.02 6959.97,6659.98 6990.03,6659.98 6960.03,6690.02 6990.03,6690.02 6764.97,6754.98 6795.03,6754.98 6179.95,6764.96 6210,6764.96 7089.97,6774.98 7120.03,6774.98 6765.03,6785.02 6795.03,6785.02 6044.95,6789.96 6075,6789.96 5754.95,6794.96 5785,6794.96 6180,6795 6210,6795 7090.03,6805.02 7120.03,6805.02 6045,6820 6075,6820 5755,6825 5785,6825 5694.95,6859.96 5725,6859.96 3909.97,6874.98 3940.03,6874.98 5695,6890 5725,6890 3910.03,6905.02 3940.03,6905.02 4079.97,6909.98 4110.03,6909.98 6544.95,6909.96 6575,6909.96 6134.95,6914.96 6165,6914.96 6889.95,6914.96 6920,6914.96 4080.03,6940.02 4110.03,6940.02 6545,6940 6575,6940 6135,6945 6165,6945 6890,6945 6920,6945 4394.97,6964.98 4425.03,6964.98 7049.97,6979.98 7080.03,6979.98 5854.95,6989.96 5885,6989.96 4395.03,6995.02 4425.03,6995.02 3556.29,7004.98 3586.35,7004.98 7050.03,7010.02 7080.03,7010.02 5855,7020 5885,7020 3556.35,7035.02 3586.35,7035.02 5724.95,7044.96 5755,7044.96 5725,7075 5755,7075 4424.97,7114.98 4455.03,7114.98 4425.03,7145.02 4455.03,7145.02 5844.95,7144.96 5875,7144.96 6764.95,7144.96 6795,7144.96 5845,7175 5875,7175 6765,7175 6795,7175
  other v2: 3600.32,4265.31 3639.69,4265.31 3600.32,4304.68 3639.69,4304.68
LED1: R15.1 U1.15 | length 2155.5
  Top Layer w10: R15.1 3784.66,6745 v1(4770,6745) ; v1(5193.11,6305) 5209.09,6289.02 5370.81,6289.02 5373.72,6286.1 U1.15
  Bottom Layer w10: v1(4770,6745) 4770,6625 5080,6315 5183.11,6315 v1(5193.11,6305)
LED2: R16.1 U1.16 | length 2092.5
  Top Layer w10: R16.1 3699.12,6705 v1(4825,6705) ; v1(5223.11,6315) 5232.32,6305.79 U1.16
  Bottom Layer w10: v1(4825,6705) 4825,6645 4955,6515 4955,6459.82 5085.81,6329.02 5209.09,6329.02 v1(5223.11,6315)
LED3: R17.1 U1.17 | length 1983.6
  Top Layer w10: R17.1 4905,6665 v1(5070,6500) ; v1(5227.01,6357.5) 5259.51,6325 5431.85,6325 U1.17
  Bottom Layer w10: v1(5070,6500) 5118.58,6500 5227.01,6391.58 v1(5227.01,6357.5)
MISO: OLED1.6 U1.27 | length 1107.6
  Top Layer w10: U1.27 5333.9,6549.9 5346.83,6562.83 5427.83,6562.83 5570,6705 5570,7170 v1(5550,7190) ; OLED1.6 5450,7355 v1(5485,7320)
  Bottom Layer w10: v1(5485,7320) 5550,7255 v1(5550,7190)
MOSI: OLED1.4 U1.28 | length 1201.3
  Top Layer w10: OLED1.4 5250,7430 5375,7305 v1(5430,7305) ; U1.28 5315,6523.11 5315,6560 5335,6580 5415,6580 5535,6700 5535,7170 v1(5515,7190)
  Bottom Layer w10: v1(5430,7305) 5515,7220 v1(5515,7190)
OIL-ADC: U1.13 U8.2 | length 1285.4
  Top Layer w10: U8.2 4528.94,5978.94 v1(4595,6045) ; v1(4940,6175) 4945,6170 5030,6170 5075,6215 5136.79,6215 5189.78,6267.99 5372.01,6267.99 5394.05,6245.95 U1.13@5432.32,6245.95
  Bottom Layer w10: v1(4595,6045) 4734.36,6045 4745.77,6056.42 4784.23,6056.42 4795.64,6045 4810,6045 v1(4940,6175)
OSC_IN: C9.2 R4.2 U1.5 X1.2 | length 425.9
  Top Layer w10: C9.2 5212.78,6082.56 R4.2 ; X1.2 5220.34,5946.8 R4.2 ; U1.5 5235.47,6125.47 5220.34,6110.34 R4.2
OSC_OUT: C8.2 R4.1 U1.6 X1.1 | length 448.7
  Top Layer w10: U1.6 5255,6187.52 5255,6125 5279.66,6100.34 R4.1 ; X1.1 5335,5890 5279.66,5945.34 R4.1 ; C8.2 5372.44,6075 R4.1
PITCH-ADC: U1.12 U9.2 | length 1445.8
  Top Layer w10: U1.12 5717.32,6187.68 5930,5975 6725.43,5975 U9.2
REST: C1.1 OLED1.5 R3.2 U1.7 U2.5 | length 2014.4
  Top Layer w10: U2.5 4925.34,6010 R3.2 5025.88,6110.54 C1.1 5025.88,6145.88 5068.71,6188.71 v1(5081.23,6188.71) ; U1.7 5275,6187.84 v1(5275,6240)
  Bottom Layer w10: v1(5081.23,6188.71) 5091.43,6198.91 5195,6198.91 5215,6218.91 5215,6220 5235,6240 v1(5275,6240) 5275,6407.52 5481.98,6614.5 5481.98,7220.5 5350,7352.48 OLED1.5
ROLL-ADC: U1.11 U9.5 | length 1452.9
  Top Layer w10: U1.11 5353.58,6243.58 v1(5355,6245) ; v1(5732.5,6087.5) 5895,5925 6090.39,5925 U9.5
  Bottom Layer w10: v1(5355,6245) 5445,6245 5487.99,6287.99 5544.52,6287.99 5572.52,6260 5650,6260 5732.5,6177.5 v1(5732.5,6087.5)
RST: U1.33 U7.1 | length 796.9
  Top Layer w10: U1.33 5215.79,6555.79 5257.01,6597.01 5402.01,6597.01 5425,6620 5425,7125.04 U7.1
S1: C22.2 E1.1 R18.1 SW2.2 U1.19 | length 2365.2
  Top Layer w10: E1.1 3700,7060 3722.07,7037.93 3747.93,7037.93 3755,7045 3755,7122.56 C22.2 3790,7229.66 R18.1 3945.64,7245 SW2.2 4350.64,6840 4778.58,6840 5253.74,6364.84 U1.19
S2: C23.2 E2.1 R19.1 SW3.2 U1.22 | length 1387.1
  Top Layer w10: U1.22 5503.9,6423.9 6040,6960 E2.1 6082.44,7110 C23.2 ; R19.1 6135,7229.66 C23.2 ; SW3.2 6305.64,7235 6235,7235 6162.56,7162.56 C23.2
S3: C24.2 E3.1 R20.1 SW4.2 U1.39 | length 2973.5
  Top Layer w10: R20.1 4080.34,4210 E3.1 4167.44,4212.44 C24.2 ; SW4.2 4250,4104.44 C24.2 ; v1(4355,4665) 4355,4317.44 C24.2 ; v1(4355,4745) 4360,4750 4360,5155 4640,5435 4640,6175 4728.58,6263.58 4784.23,6263.58 4954.54,6433.9 5060.1,6433.9 5066.72,6427.28 5094.3,6427.28 U1.39
  Bottom Layer w10: v1(4355,4665) v1(4355,4745)
S4: C25.2 E4.1 R21.1 SW5.2 U1.46 | length 1679.2
  Top Layer w10: SW5.2 4990,5254.44 C25.2 4987.44,5345 E4.1 4889.66,5345.34 R21.1 4729.66,5345.34 4680,5395 4680,6015 4725,6060 4865,6060 4890,6085 4890,6265 4914.49,6289.49 5094.29,6289.49 U1.46
S5: C26.2 E5.1 R22.1 SW6.2 U1.41 | length 6449.4
  Top Layer w10: v1(5045,7512.01) 5622.81,7512.01 5669.02,7465.81 5669.02,7330.98 5715,7285 6014.02,7285 6015,7284.02 6019.19,7284.02 6029.19,7294.02 6345.81,7294.02 6364.02,7275.81 6364.02,6935 6920,6379.02 v1(6920,5455) ; U1.41 5174.53,6384.53 v1(5176.57,6386.57) ; R22.1 5654.66,5355.34 E5.1 5757.44,5350 C26.2 5774.13,5333.31 SW6.2 5777.7,5250 v1(5960,5250)
  Bottom Layer w10: v1(5045,7512.01) 4994.45,7461.46 4994.45,7396.99 4970,7372.54 4970,7135 4980,7125 4980,6519.82 5059.82,6440 5123.14,6440 v1(5176.57,6386.57) ; v1(5960,5250) 6715,5250 v1(6920,5455)
S6: C27.2 E6.1 R23.1 SW7.2 U1.40 | length 6633.1
  Top Layer w10: v1(4740,6910) 4850,7020 4850,7450 4885,7485 5630,7485 5655,7460 5655,7295 5680,7270 6025,7270 6035,7280 6340,7280 6350,7270 6350,6515 6530,6335 6760,6335 6860,6235 6860,5365 6695,5200 v1(6670,5200) ; v1(4960,6400.91) 4963.3,6404.21 U1.40 ; R23.1 6314.66,4565.34 E6.1 6397.44,4565 C27.2 ; SW7.2 6405,4474.44 C27.2 ; v1(6530,5165) 6530,4682.44 C27.2
  Bottom Layer w10: v1(4740,6910) 4740,6620.91 v1(4960,6400.91) ; v1(6530,5165) 6635,5165 v1(6670,5200)
S7: C28.2 E7.1 R24.1 SW8.2 U1.45 | length 4285.1
  Top Layer w10: v1(5070,5460) 5310,5220 5310,5065 5376.27,4998.73 cw(c5228.5,4263.11) 5931.63,4525 6080,4525 6120,4485 6120,4205 6250,4075 6549.66,4075 R24.1 6650.34,4075.34 E7.1 6762.44,4080 C28.2 SW8.2 ; U1.45 5125.25,6305.79 5138.19,6292.85 5151.85,6292.85 v1(5155.2,6289.5)
  Bottom Layer w10: v1(5070,5460) 4540,5990 4540,6150 4653.58,6263.58 4826.42,6263.58 4846.49,6243.51 4983.51,6243.51 5029.5,6289.5 v1(5155.2,6289.5)
S8: C29.2 E8.1 R25.1 SW9.2 U1.42 | length 2572.6
  Top Layer w10: R25.1 4124.66,4670 E8.1 4162.44,4672.44 C29.2 ; SW9.2 4250,4569.44 C29.2 ; U1.42 5097.52,6365 4925,6365 4835,6275 4835,6170 4825,6160 4705,6160 4675,6130 4675,6055 4660,6040 4660,5410 4410,5160 4410,4760 4322.44,4672.44 C29.2
S9: C30.2 E9.1 R26.1 SW10.2 U1.43 | length 5933.4
  Top Layer w10: U1.43 5170.16,6345.16 v1(5180,6355) ; v1(6780,4595) 6814.66,4560.34 R26.1 6990.34,4560.34 E9.1 7097.44,4570 C30.2 7110,4464.09 SW10.2
  Bottom Layer w10: v1(5180,6355) 5180,6357.48 5199.56,6377.05 5199.56,6396.09 5186.09,6409.56 5173.4,6409.56 5128.95,6454.02 5120.98,6454.02 5089.02,6485.98 5088.5,6485.98 5079.52,6477.01 5060.48,6477.01 5047.01,6490.48 5047.01,6527.99 5005,6570 5005,7200 5105,7300 5105,7500 5112.07,7507.07 5602.93,7507.07 5645,7465 5645,7269.82 5657.99,7256.83 5657.99,7042.01 6460,6240 6460,6000 7000,5460 7000,4815 v1(6780,4595)
S10: C31.2 E10.1 R27.1 SW11.2 U1.29 | length 2681.5
  Top Layer w10: U1.29 5297.91,6518.94 5297.91,6491.36 5319.27,6470 5320,6470 v1(5345,6445) ; v1(6110,5380) 6240,5250 6480,5250 6557.01,5172.99 6557.01,5059.23 6585,5031.24 R27.1 6670.34,5020.34 E10.1 6767.44,5025 C31.2 ; SW11.2 C31.2
  Bottom Layer w10: v1(5345,6445) 5475,6315 5795,6315 6110,6000 v1(6110,5380)
SCK: OLED1.3 U1.26 | length 1525
  Top Layer w10: OLED1.3 5165,7435 5327.99,7272.01 5579.52,7272.01 5587.52,7280 v1(5615,7280) ; U1.26 5353.58,6491.36 5363.13,6481.81 5406.81,6481.81 5635,6710 v1(5635,7190)
  Bottom Layer w10: v1(5615,7280) 5635,7260 v1(5635,7190)
SWCLK: U1.37 U2.2 | length 396.2
  Top Layer w10: U2.2 4767.52,6310 4920.79,6463.27 U1.37
SWDIO: U1.34 U2.3 | length 810.3
  Top Layer w10: v1(5196.1,6455) U1.34
  Bottom Layer w10: U2.3 4778.74,6196.26 4928.74,6196.26 4930.48,6197.99 4949.52,6197.99 4967.52,6180 5040,6180 5072.93,6212.93 5185,6212.93 5255,6282.93 5255,6396.1 v1(5196.1,6455)
UART_RX: U1.31 U7.5 | length 950.8
  Top Layer w10: U7.5 5126.04,6973.96 5182.99,6917.01 5302.81,6917.01 5355,6864.82 v1(5355,6624.02) ; v1(5255,6460) 5255,6522.16 U1.31
  Bottom Layer w10: v1(5255,6460) 5255,6524.02 5327.99,6597.01 5329.52,6597.01 5342.99,6610.48 5342.99,6612.01 v1(5355,6624.02)
UART_TX: U1.30 U7.4 | length 890.6
  Top Layer w10: U7.4 5204.78,6975.22 5248.98,6931.02 5308.62,6931.02 5385,6854.64 v1(5385,6640) ; U1.30 5274.84,6480.16 v1(5290,6465)
  Bottom Layer w10: v1(5290,6465) 5290,6530 5361.02,6601.02 5364.52,6601.02 5385,6621.5 v1(5385,6640)
VCC: C13.2 L2.1 R6.1 R13.2 SW1.2 U4.3 | length 561.8
  Top Layer w19.68: U4.3 3645,4104.66 R6.1 3640,4099.66 3640,4035 3617.45,4012.45 L2.1 3560,3927.44 C13.2 3559.66,3912.9 R13.2 3630.01,3830 SW1.2
pads on no net: SW1.3 SW2.3 SW2.4 SW3.3 SW3.4 SW4.1 SW4.3 SW5.1 SW5.3 SW6.1 SW6.3 SW7.1 SW7.3 SW8.1 SW8.3 SW9.1 SW9.3 SW10.1 SW10.3 SW11.1 SW11.3 U1.2 U1.3 U1.4 U1.10 U1.18 U1.21 U1.38 U8.0 U9.0

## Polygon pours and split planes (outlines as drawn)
GND on Top Layer (solid, remove dead copper, pour order 0): 3000,7910 7655,7910 7655,3000 3000,3000
GND on Bottom Layer (solid, remove dead copper, pour order 2): 3135,7720 7460,7720 7460,3170 3135,3170

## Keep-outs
Board Outline Layer:
  region: 5225,6220 5225,6130 5200.58,6130 5200,6130.58 5080.58,6130.58 5080.58,6080.58 5070,6070 5070,6012.14 5094.75,5987.39 5094.75,5968.11 5093.11,5968.11 5050,5925 5050,5855 5105,5800 5410,5800 5470,5860 5470,5927.44 5422.85,5974.59 5422.85,6032.85 5425,6035 5425,6120 5414.42,6130.58 5269.86,6130.58 5265,6135.44 5265,6220
  lines w10: 4495,4261.61 cw(c3877.5,4237.56) 3260,4261.61 3260,6994.53 cw(c3605.96,6972.35) 3618.9,7318.78 4736.38,7318.78 4736.38,7555 5720.63,7555 5720.63,7318.78 6872.4,7318.78 ; 4495,4263.11 cw(c5228.5,4263.11) 5962.01,4263.11 ; 5962.01,4261.61 ccw(c6579.51,4237.56) 7197.01,4261.61 ; 6872.4,7318.31 cw(c6850.22,6972.35) 7196.65,6959.41 7196.65,4261.61

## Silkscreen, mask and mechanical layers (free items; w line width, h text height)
Top Silkscreen Layer:
  text "左航向角" at 4240,7220 h59.06
  text "右航向角" at 6580,7220 h59.06
  text "失控指示灯" at 3655,6890 h59.06
  text "飞机低电量" at 3660,6765 h59.06
  text "手柄低电量" at 3670,6630 h59.06
  text "电源指示灯" at 3415,5115 h59.06
  text "飞机解锁" at 5720,4970 h59.06
  text "飞机上锁" at 4435,4960 h59.06
  text "飞机微调" at 6460,4365 h59.06
  text "关" at 3605,3995 h39.37
  text "开" at 3610,3720 h39.37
